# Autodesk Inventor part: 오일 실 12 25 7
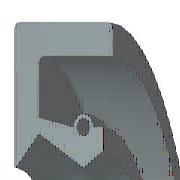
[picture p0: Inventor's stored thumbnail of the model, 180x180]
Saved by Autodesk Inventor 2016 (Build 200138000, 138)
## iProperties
IsCustomPart: 1
Created: 2012-02
Part Number: 오일 실 12 25 7
Material: 고무
Description: 오일-실
Document SubType Name: Modeling
Standard: KS B 2804
Designer: test
Standards Organization: KS
Language: ko-KR
Size Designation: D - 12 25 7
Categories: <MemberInstance><Categories><Category DisplayName="샤프트 부품" InternalName="7f7aeb1f-a693-4053-b835-cee3144e0d98" Mnemonic="SHFT"><Category DisplayName="실링" Intern
Density: 0.93 g/cm^3
Appearance: 고무 - 검은색 - 버전 1.1
Author: test
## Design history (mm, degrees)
revolve "본체" stored, may be unused: angle "d17" = 90 deg
revolve "스프링1" stored, may be unused: angle "d18" = 90 deg
body "Solid1"
sketch "스케치1"
  geometry: L1 (0, 12.5)-(7, 12.5); L2 (7, 10.75)-(1.75, 10.75); L3 (1.75, 7.75)-(4.9, 6); L4 (4.9, 6)-(0, 6); L5 (0, 0)-(9.586, 0) reference; L6 (4.9, 6)-(6.3, 6.875); L7 (0, 18)-(0, -3) reference; L8 (-1.941, 0)-(11.507, 0) reference; L9 (4.2, 8.1)-(1.75, 8.59); L10 (1.75, 8.59)-(1.75, 10.75); L11 (0, 12.5)-(0, 6.088); L12 (4.9, 6)-(0, 6); L13 (1.75, 7.75)-(0.152, 6.028); L14 (7, 12.5)-(7, 10.75); L15 (5.6, 8.1)-(6.3, 8.1); L16 (6.3, 8.1)-(6.3, 6.875); C1 r 0.455 at (4.9, 8.1); A1 r 0.7 centre (4.9, 8.1) between (5.6, 8.1) and (4.2, 8.1); A2 r 0.088 centre (0.088, 6.088) between (0, 6.088) and (0.152, 6.028); 1 further point
  constraints: 28 end point, 5 horizontal alignment, 5 point on line, 4 point on circle, 4 vertical alignment, 3 centre point, 3 tangent, 2 collinear, 2 horizontal, 2 perpendicular, 1 coincident, 1 parallel
  dimensions: "d0" = 25 diameter of L1 L5 (= SD2); "d1" = 1.75 distance of L1.end L2.start (= SD); "d2" = 0.91 diameter of C1 (= SPDI); "d3" = 1.4 diameter of A1 (= SPDA); "d4" = 12 diameter of L3.end L5 (= NND); "d5" = 15.5 diameter of L3.start L5 (= TKDM); "d7" = 17.18 diameter of L9.end L5 (= TKDM + 0.24 x SWDT); "d8" = 1.75 distance between parallel lines of L11 L10 (= SD); "d9" = 4.9 distance from line of L11 C1.centre (= SPDST); "d10" = 16.2 diameter of C1.centre L5 (= HLDM); "d11" = 0.0875 radius of A2 (= 0.25 x LAB); "d12" = 6.3 distance between parallel lines of L11 L16 (= SDI); "d13" = 13.75 diameter of L6.end L5 (= ABDM); "d14" = 7 distance from line of L11 L1.end (= SWDT)
fillet "모깎기1" dims "d6" = 0.3 (= RR)
other parameters: "SD2" = 25 [user parameter; used in 1 equation term], "SWDT" = 7 [user parameter; used in 2 equation terms], "RR" = 0.3 [user parameter; used in 1 equation term], "SD" = 1.75 [user parameter; used in 2 equation terms], "NND" = 12 [user parameter; used in 1 equation term], "SPDA" = 1.4 [user parameter; used in 1 equation term], "SPDI" = 0.91 [user parameter; used in 1 equation term], "TKDM" = 15.5 [user parameter; used in 2 equation terms], "HLDM" = 16.2 [user parameter; used in 1 equation term], "ABDM" = 13.75 [user parameter; used in 1 equation term], "SDI" = 6.3 [user parameter; used in 1 equation term], "SPDST" = 4.9 [user parameter; used in 1 equation term], "LAB" = 0.35 [user parameter; used in 1 equation term], "d15" = 0, "d16" = 0, "d19" = 0
